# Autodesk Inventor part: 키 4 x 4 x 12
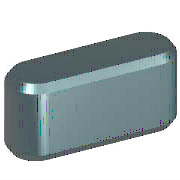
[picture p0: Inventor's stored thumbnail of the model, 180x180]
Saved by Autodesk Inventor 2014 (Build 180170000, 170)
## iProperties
IsCustomPart: 1
Created: 2012-02
Part Number: 키 4 x 4 x 12
Material: 강철, 연강
Description: 키 및 해당 키홈
Document SubType Name: Modeling
Standard: KS B 1311
Designer: mduedu
Standards Organization: KS
Language: ko-KR
Size Designation: 4 x 4 x 12
Categories: <MemberInstance><Categories><Category DisplayName="샤프트 부품" InternalName="7f7aeb1f-a693-4053-b835-cee3144e0d98" Mnemonic="SHFT"><Category DisplayName="키" Interna
Density: 1 g/cm^3
Appearance: Yellow
Author: mduedu
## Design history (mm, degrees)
sketch "스케치1"
  geometry: L1 (2, 2)-(10, 2); L2 (10, -2)-(2, -2); L3 (0, 9.4)-(0, -7.4) reference; L4 (-5, 0)-(30, 0) reference; L5 (12, 0)-(12, 7); A1 r 2 centre (2, 0) between (2, 2) and (2, -2); A2 r 2 centre (10, 0) between (10, -2) and (10, 2)
  constraints: 6 end point, 5 point on circle, 4 tangent, 3 point on line, 2 centre point, 1 horizontal, 1 parallel, 1 perpendicular
  dimensions: "d0" = 2 radius of A1 (= 0.5 x PB); "d13" = 2 radius of A2 (= 0.5 x PB); "d14" = 12 distance between parallel lines of L5 L3 (= NLG)
extrude "본체1" new body sketch "스케치1" taper "d3" = 0 deg; stored distance "d4" = 10
workplane "Work Plane3"
body "Solid1"
workplane "Work Plane1"
workplane "Work Plane2"
chamfer "모따기1" distance "d8" = 0.25 (= PHH); stored, may be unused: second distance "d9" = 0.25 (= PHH), angle "d15" = 45 deg
other parameters: "d1" = -2.5 (= -PNT), "d2" = 1.5 (= PH - PNT), "NLG" = 12 [user parameter; used in 3 equation terms], "PB" = 4 [user parameter; used in 2 equation terms], "PNT" = 2.5 [user parameter; used in 2 equation terms], "PH" = 4 [user parameter; used in 1 equation term], "PHH" = 0.25 [user parameter; used in 2 equation terms], "d10" = 0, "d16" = 0, "d17" = 0, "d18" = 0, "PLB2" = 12 (= NLG) [user parameter], "WDMAX" = 12 [user parameter], "PLB1" = 12 (= NLG) [user parameter], "RR" = 0.08 [user parameter], "PUEB" = 1.8 [user parameter]
